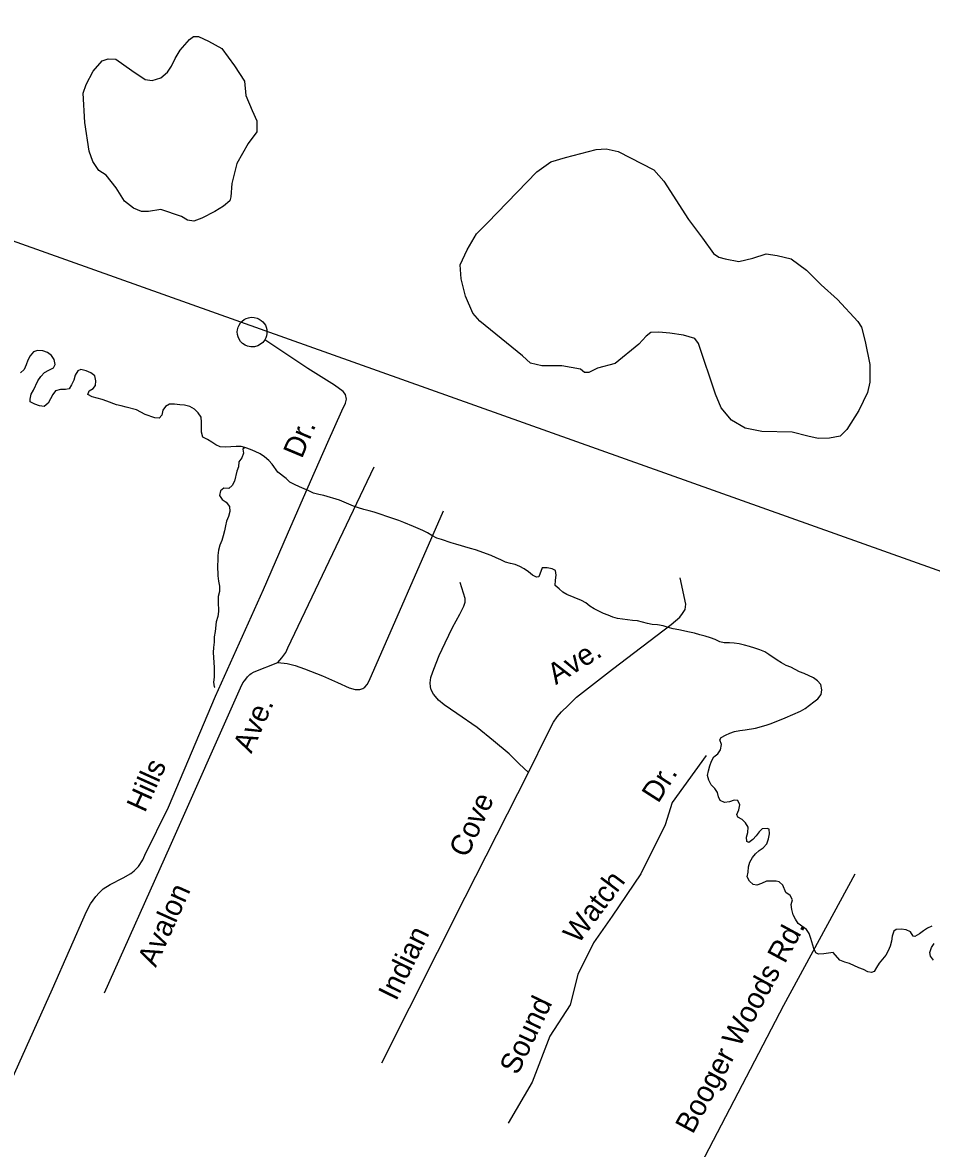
# Model space of a CAD drawing. Extents: x 2308163 to 2335412, y -96774 to 127732.
# Drawn here: x 2325975.4 to 2326033, y 123265.8 to 123337.2 of the extents above; entities that cross this region are included whole.
import ezdxf

# ---------------------------------------------------------------- set-up
doc = ezdxf.new("R2010")
doc.units = 0
for name, color, linetype in [('Old_Level_10', 7, 'Continuous'), ('Old_Level_35', 7, 'Continuous'), ('Old_Level_59', 7, 'Continuous'), ('Old_Level_60', 7, 'Continuous'), ('Old_Level_61', 7, 'Continuous'), ('Old_Level_63', 7, 'Continuous')]:
    doc.layers.add(name, color=color, linetype=linetype)

msp = doc.modelspace()

# ---------------------------------------------------------------- linework, layer by layer
at = {"layer": 'Old_Level_35'}
for points in [[(2325990.731, 123317.12), (2325990.598, 123316.949), (2325990.456, 123316.834), (2325990.282, 123316.732), (2325990.067, 123316.674), (2325989.844, 123316.669), (2325989.64, 123316.712), (2325989.478, 123316.785), (2325989.323, 123316.889), (2325989.2, 123317.015), (2325989.098, 123317.169), (2325989.032, 123317.302), (2325988.999, 123317.46), (2325988.982, 123317.623), (2325988.998, 123317.761), (2325989.033, 123317.924), (2325989.102, 123318.058), (2325989.19, 123318.197), (2325989.295, 123318.307), (2325989.417, 123318.405), (2325989.558, 123318.47), (2325989.688, 123318.52), (2325989.875, 123318.553), (2325990.054, 123318.542), (2325990.241, 123318.502), (2325990.383, 123318.438), (2325990.509, 123318.341), (2325990.603, 123318.269), (2325990.697, 123318.155), (2325990.767, 123318.05), (2325990.816, 123317.92), (2325990.853, 123317.782), (2325990.866, 123317.657), (2325990.867, 123317.51), (2325990.843, 123317.38), (2325990.803, 123317.25), (2325990.731, 123317.12)], [(2325977.276, 123275.956), (2325979.43, 123280.857), (2325979.687, 123281.344), (2325979.853, 123281.578), (2325980.018, 123281.819), (2325980.23, 123282.06), (2325980.482, 123282.294), (2325980.934, 123282.57), (2325981.758, 123283), (2325982.249, 123283.269), (2325982.455, 123283.437), (2325982.733, 123283.718), (2325983.004, 123284.146), (2325983.123, 123284.446), (2325984.62, 123287.478), (2325987.602, 123294.521), (2325990.652, 123301.291), (2325992.165, 123304.797), (2325993.623, 123308.139), (2325994.727, 123310.622), (2325995.615, 123312.62), (2325995.852, 123313.105), (2325995.907, 123313.365), (2325995.849, 123313.645), (2325995.698, 123313.831), (2325995.139, 123314.238), (2325993.457, 123315.31), (2325990.731, 123317.12)], [(2325991.555, 123296.659), (2325991.813, 123296.947), (2325992.058, 123297.301), (2325992.19, 123297.582), (2325997.651, 123309.069)], [(2325991.555, 123296.659), (2325992.155, 123296.596), (2325992.648, 123296.472), (2325993.256, 123296.255), (2325994.384, 123295.821), (2325995.345, 123295.393), (2325996.073, 123295.043), (2325996.46, 123294.952), (2325996.76, 123294.947), (2325996.946, 123295.008), (2325997.072, 123295.088), (2325997.218, 123295.262), (2325997.343, 123295.503), (2326002.055, 123306.276)], [(2326007.445, 123289.691), (2326008.645, 123292.142), (2326009.028, 123292.863), (2326009.252, 123293.211), (2326009.524, 123293.519), (2326009.948, 123293.94), (2326010.485, 123294.456), (2326012.761, 123296.226), (2326016.491, 123299.07), (2326017.035, 123299.539), (2326017.207, 123299.759), (2326017.366, 123300.02), (2326017.424, 123300.347), (2326017.062, 123302.018)], [(2326007.445, 123289.691), (2326006.849, 123290.234), (2326006.213, 123290.864), (2326005.216, 123291.698), (2326004.18, 123292.539), (2326002.903, 123293.419), (2326002.101, 123293.968), (2326001.739, 123294.272), (2326001.545, 123294.511), (2326001.424, 123294.65), (2326001.27, 123294.923), (2326001.235, 123295.122), (2326001.201, 123295.375), (2326001.253, 123295.695), (2326001.377, 123296.062), (2326001.594, 123296.623), (2326001.778, 123297.11), (2326002.154, 123297.905), (2326002.629, 123298.873), (2326003.091, 123299.715), (2326003.348, 123300.236), (2326003.427, 123300.489), (2326003.439, 123300.723), (2326003.11, 123301.725)], [(2325980.562, 123275.713), (2325984.732, 123285), (2325989.198, 123295.055), (2325989.343, 123295.369), (2325989.436, 123295.503), (2325989.522, 123295.603), (2325989.641, 123295.744), (2325989.787, 123295.891), (2325989.873, 123295.958), (2325990.052, 123296.059), (2325991.555, 123296.659)], [(2326018.699, 123290.764), (2326016.555, 123287.779), (2326016.099, 123286.367), (2326014.563, 123283.259), (2326012.736, 123280.569), (2326011.555, 123278.876), (2326010.567, 123276.871), (2326010.093, 123274.95), (2326008.8, 123272.955), (2326007.679, 123270.037), (2326006.152, 123267.439)], [(2325998.138, 123271.265), (2326003.434, 123281.783), (2326007.445, 123289.691)], [(2326017.062, 123262.313), (2326023.627, 123274.917), (2326028.142, 123283.26)], [(2325965.386, 123249.929), (2325969.926, 123259.265), (2325974.397, 123269.56), (2325977.276, 123275.956)]]:
    msp.add_lwpolyline(points, dxfattribs=at)
at = {"layer": 'Old_Level_59'}
msp.add_lwpolyline([(2325989.467, 123310.289), (2325989.331, 123310.186), (2325989.381, 123309.921), (2325989.282, 123309.629), (2325989.084, 123309.382), (2325989.061, 123309.073), (2325988.956, 123308.782), (2325988.806, 123308.157), (2325988.672, 123307.872), (2325988.456, 123307.686), (2325988.14, 123307.707), (2325987.933, 123307.532), (2325987.868, 123307.249), (2325988.034, 123306.989), (2325988.29, 123306.818), (2325988.486, 123306.552), (2325988.512, 123306.231), (2325988.422, 123305.924), (2325988.31, 123305.623), (2325988.23, 123305.321), (2325988.175, 123305.003), (2325988.093, 123304.691), (2325987.997, 123304.394), (2325987.89, 123304.103), (2325987.794, 123303.786), (2325987.762, 123303.452), (2325987.763, 123303.142), (2325987.733, 123302.798), (2325987.747, 123302.142), (2325987.803, 123301.81), (2325987.865, 123301.492), (2325987.851, 123301.158), (2325987.784, 123300.85), (2325987.773, 123300.525), (2325987.787, 123299.884), (2325987.754, 123299.565), (2325987.651, 123299.244), (2325987.595, 123298.621), (2325987.525, 123298.288), (2325987.513, 123297.948), (2325987.489, 123297.613), (2325987.452, 123297.284), (2325987.507, 123296.652), (2325987.512, 123296.337), (2325987.53, 123296.032), (2325987.52, 123295.727), (2325987.489, 123295.418), (2325987.529, 123295.117), (2325987.559, 123295.096)], dxfattribs=at)
at = {"layer": 'Old_Level_60'}
for points in [[(2325989.467, 123310.289), (2325989.224, 123310.363), (2325988.909, 123310.364), (2325988.578, 123310.329), (2325988.238, 123310.321), (2325987.903, 123310.327), (2325987.625, 123310.454), (2325987.367, 123310.625), (2325987.1, 123310.792), (2325986.813, 123310.954), (2325986.726, 123311.262), (2325986.709, 123311.888), (2325986.688, 123312.208), (2325986.515, 123312.494), (2325986.267, 123312.726), (2325985.972, 123312.899), (2325985.643, 123312.981), (2325985.339, 123313.002), (2325985.003, 123313.039), (2325984.696, 123313.044), (2325984.433, 123312.881), (2325984.264, 123312.658), (2325984.211, 123312.34), (2325984.04, 123312.152), (2325983.761, 123312.167), (2325983.151, 123312.391), (2325982.597, 123312.685), (2325981.945, 123312.84), (2325981.623, 123312.932), (2325981.325, 123313.003), (2325980.713, 123313.228), (2325980.414, 123313.324), (2325979.79, 123313.503), (2325979.506, 123313.65), (2325979.6, 123313.886), (2325979.861, 123314.034), (2325979.997, 123314.213), (2325980.024, 123314.527), (2325979.963, 123314.834), (2325979.714, 123315.025), (2325979.415, 123315.142), (2325979.079, 123315.23), (2325978.883, 123315.145), (2325978.713, 123314.872), (2325978.623, 123314.56), (2325978.487, 123314.27), (2325978.333, 123314.006), (2325978.098, 123313.958), (2325977.785, 123313.959), (2325977.469, 123313.878), (2325977.289, 123313.656), (2325976.998, 123313.112), (2325976.746, 123312.897), (2325976.442, 123312.923), (2325976.156, 123313.029), (2325975.87, 123313.176), (2325975.856, 123313.36), (2325975.919, 123313.667), (2325976.067, 123313.931), (2325976.347, 123314.521), (2325976.531, 123314.789), (2325976.765, 123315.04), (2325977.037, 123315.189), (2325977.33, 123315.336), (2325977.445, 123315.551), (2325977.388, 123315.873), (2325977.203, 123316.123), (2325976.96, 123316.309), (2325976.652, 123316.411), (2325976.33, 123316.432), (2325976.061, 123316.366), (2325975.863, 123316.113), (2325975.709, 123315.834), (2325975.616, 123315.537), (2325975.49, 123315.232), (2325975.238, 123315.017)], [(2325995.455, 123306.952), (2325994.478, 123307.25), (2325994.149, 123307.317), (2325993.817, 123307.4), (2325993.512, 123307.532), (2325993.22, 123307.674), (2325992.928, 123307.806), (2325992.603, 123307.945), (2325992.312, 123308.102), (2325992.074, 123308.324), (2325991.563, 123308.722), (2325991.195, 123309.233), (2325990.981, 123309.464), (2325990.719, 123309.702), (2325990.443, 123309.899), (2325990.125, 123310.047), (2325989.82, 123310.17), (2325989.525, 123310.271), (2325989.467, 123310.289)], [(2326014.359, 123299.293), (2326014.035, 123299.325), (2326013.402, 123299.402), (2326013.08, 123299.449), (2326012.78, 123299.536), (2326012.498, 123299.662), (2326012.197, 123299.774), (2326011.597, 123300.054), (2326011.335, 123300.226), (2326011.076, 123300.433), (2326010.794, 123300.585), (2326009.876, 123300.962), (2326009.616, 123301.123), (2326009.376, 123301.32), (2326009.14, 123301.546), (2326009.156, 123301.871), (2326009.193, 123302.185), (2326009.161, 123302.491), (2326008.933, 123302.605), (2326008.624, 123302.667), (2326008.309, 123302.667), (2326008.104, 123302.08), (2326007.951, 123302.06), (2326007.706, 123302.205), (2326007.453, 123302.407), (2326007.175, 123302.605), (2326006.889, 123302.752), (2326006.603, 123302.863), (2326006.292, 123302.935), (2326005.986, 123303.027), (2326005.682, 123303.159), (2326005.384, 123303.302), (2326005.069, 123303.435), (2326004.092, 123303.793), (2326003.76, 123303.896), (2326002.84, 123304.152), (2326002.541, 123304.243), (2326001.937, 123304.462), (2326001.626, 123304.549), (2326001.31, 123304.702), (2326001.046, 123304.874), (2326000.747, 123305.027), (2326000.149, 123305.281), (2325999.532, 123305.526), (2325999.215, 123305.659), (2325998.913, 123305.771), (2325997.651, 123306.2), (2325997.345, 123306.282), (2325997, 123306.36), (2325996.668, 123306.463), (2325996.355, 123306.575), (2325996.056, 123306.692), (2325995.766, 123306.824), (2325995.455, 123306.952)], [(2326021.386, 123283.69), (2326021.466, 123283.998), (2326021.648, 123284.281), (2326021.833, 123284.524), (2326022.064, 123284.729), (2326022.319, 123284.913), (2326022.538, 123285.165), (2326022.649, 123285.476), (2326022.725, 123285.783), (2326022.705, 123286.089), (2326022.56, 123286.13), (2326022.244, 123286.115), (2326022.052, 123285.918), (2326021.867, 123285.671), (2326021.67, 123285.439), (2326021.405, 123285.235), (2326021.275, 123285.3), (2326021.256, 123285.59), (2326021.344, 123285.882), (2326021.361, 123286.217), (2326021.204, 123286.491), (2326020.994, 123286.707), (2326020.699, 123286.859), (2326020.639, 123287.024), (2326020.781, 123287.309), (2326020.827, 123287.627), (2326020.702, 123287.911), (2326020.477, 123287.929), (2326020.185, 123287.812), (2326019.869, 123287.787), (2326019.582, 123287.909), (2326019.489, 123288.146), (2326019.427, 123288.423), (2326019.253, 123288.677), (2326019.009, 123288.904), (2326018.879, 123289.188), (2326018.788, 123289.496), (2326018.849, 123289.794), (2326018.932, 123290.101), (2326019.044, 123290.402), (2326019.198, 123290.681), (2326019.442, 123290.866), (2326019.612, 123291.124), (2326019.664, 123291.448), (2326019.567, 123291.756), (2326019.651, 123291.906), (2326019.923, 123292.054), (2326020.209, 123292.171), (2326020.497, 123292.273), (2326020.837, 123292.342), (2326021.178, 123292.386), (2326021.824, 123292.491), (2326022.497, 123292.681), (2326022.817, 123292.782), (2326023.718, 123293.147), (2326024.688, 123293.561), (2326024.979, 123293.744), (2326025.25, 123293.958), (2326025.527, 123294.162), (2326025.772, 123294.357), (2326025.99, 123294.619), (2326026.029, 123294.927), (2326025.976, 123295.259), (2326025.756, 123295.491), (2326025.498, 123295.682), (2326024.915, 123295.962), (2326024.62, 123296.073), (2326024.34, 123296.21), (2326024.063, 123296.357), (2326023.772, 123296.474), (2326023.475, 123296.626), (2326023.206, 123296.798), (2326022.68, 123297.172), (2326022.42, 123297.338), (2326022.107, 123297.466), (2326021.785, 123297.569), (2326021.458, 123297.666), (2326021.133, 123297.749), (2326020.803, 123297.841), (2326020.487, 123297.883), (2326020.177, 123297.903), (2326019.836, 123297.905), (2326019.572, 123297.975), (2326019.268, 123298.123), (2326018.967, 123298.23), (2326018.629, 123298.328), (2326018.31, 123298.405), (2326017.968, 123298.508), (2326017.652, 123298.59), (2326016.964, 123298.731), (2326016.62, 123298.793), (2326016.288, 123298.881), (2326015.967, 123298.989), (2326015.623, 123299.036), (2326015.282, 123299.068), (2326014.977, 123299.124), (2326014.67, 123299.221), (2326014.359, 123299.293)], [(2326033.012, 123279.931), (2326032.732, 123279.808), (2326032.47, 123279.645), (2326032.219, 123279.445), (2326031.934, 123279.272), (2326031.832, 123279.306), (2326031.652, 123279.571), (2326031.384, 123279.708), (2326031.064, 123279.739), (2326030.741, 123279.735), (2326030.587, 123279.628), (2326030.499, 123279.306), (2326030.445, 123278.978), (2326030.369, 123278.67), (2326030.231, 123278.381), (2326030.083, 123278.106), (2326029.668, 123277.597), (2326029.507, 123277.318), (2326029.34, 123277.065), (2326029.173, 123276.989), (2326028.959, 123277.047), (2326028.675, 123277.179), (2326028.37, 123277.301), (2326027.788, 123277.565), (2326027.481, 123277.657), (2326027.177, 123277.774), (2326026.75, 123278.267), (2326026.163, 123278.175), (2326025.827, 123278.151), (2326025.662, 123278.248), (2326025.529, 123278.522), (2326025.344, 123279.164), (2326025.228, 123279.463), (2326025.062, 123279.727), (2326024.527, 123280.112), (2326024.355, 123280.372), (2326024.218, 123280.666), (2326024.13, 123280.984), (2326024.098, 123281.31), (2326024.166, 123281.608), (2326024.023, 123281.877), (2326023.761, 123282.079), (2326023.561, 123282.528), (2326023.337, 123282.749), (2326023.144, 123282.797), (2326022.521, 123282.782), (2326022.202, 123282.651), (2326021.907, 123282.544), (2326021.679, 123282.573), (2326021.451, 123282.794), (2326021.3, 123283.068), (2326021.367, 123283.371), (2326021.386, 123283.69)], [(2326033.105, 123277.783), (2326032.926, 123278.028), (2326032.873, 123278.269), (2326032.977, 123278.58), (2326033.155, 123278.828)]]:
    msp.add_lwpolyline(points, dxfattribs=at)
at = {"layer": 'Old_Level_61'}
for points in [[(2325990.222, 123330.302), (2325989.675, 123329.574), (2325988.96, 123328.293), (2325988.639, 123327.024), (2325988.587, 123326.187), (2325988.51, 123325.941), (2325988.112, 123325.584), (2325987.561, 123325.262), (2325986.738, 123324.823), (2325986.223, 123324.643), (2325985.834, 123324.707), (2325985.447, 123324.939), (2325984.145, 123325.38), (2325983.355, 123325.26), (2325982.915, 123325.25), (2325982.415, 123325.46), (2325981.829, 123325.902), (2325981.303, 123326.759), (2325980.684, 123327.568), (2325980.209, 123327.858), (2325979.821, 123328.426), (2325979.604, 123329.083), (2325979.32, 123330.892), (2325979.222, 123332.76), (2325979.403, 123333.308), (2325979.848, 123334.156), (2325980.425, 123334.802), (2325980.795, 123334.942), (2325981.284, 123334.92), (2325982.299, 123334.194), (2325983.158, 123333.62), (2325983.594, 123333.57), (2325984.133, 123333.734), (2325984.561, 123334.09), (2325984.823, 123334.482), (2325985.053, 123334.962), (2325985.372, 123335.49), (2325985.95, 123336.161), (2325986.211, 123336.35), (2325986.536, 123336.344), (2325987.171, 123336.048), (2325988.011, 123335.597), (2325988.804, 123334.487), (2325989.441, 123333.525), (2325989.526, 123332.613), (2325989.932, 123331.664), (2325990.233, 123331.013), (2325990.222, 123330.302)], [(2326029.073, 123314.425), (2326028.932, 123313.78), (2326028.384, 123312.64), (2326027.622, 123311.442), (2326027.195, 123311.005), (2326026.52, 123310.88), (2326025.804, 123310.865), (2326025.137, 123310.999), (2326024.153, 123311.257), (2326022.224, 123311.308), (2326021.179, 123311.507), (2326020.301, 123312.015), (2326019.653, 123312.804), (2326019.29, 123313.681), (2326018.222, 123316.878), (2326017.978, 123317.201), (2326017.269, 123317.419), (2326016.395, 123317.551), (2326015.7, 123317.605), (2326015.195, 123317.592), (2326014.909, 123317.353), (2326014.43, 123316.851), (2326012.931, 123315.622), (2326011.811, 123315.315), (2326011.267, 123315.04), (2326010.993, 123315.049), (2326010.746, 123315.256), (2326009.551, 123315.47), (2326008.286, 123315.462), (2326007.569, 123315.635), (2326007.054, 123316.099), (2326004.356, 123318.311), (2326003.907, 123318.81), (2326003.44, 123319.893), (2326003.178, 123320.989), (2326003.114, 123321.87), (2326003.564, 123322.825), (2326004.154, 123323.836), (2326004.853, 123324.529), (2326007.962, 123327.775), (2326008.865, 123328.41), (2326009.79, 123328.672), (2326011.735, 123329.195), (2326012.356, 123329.224), (2326013.117, 123329.05), (2326015.388, 123327.89), (2326016.03, 123327.177), (2326017.591, 123324.755), (2326018.475, 123323.566), (2326019.157, 123322.582), (2326019.497, 123322.362), (2326019.905, 123322.252), (2326020.782, 123322.094), (2326021.667, 123322.287), (2326022.509, 123322.578), (2326023.208, 123322.458), (2326024.092, 123322.249), (2326025.061, 123321.525), (2326025.99, 123320.604), (2326027.032, 123319.684), (2326028.307, 123318.288), (2326028.543, 123317.929), (2326028.789, 123317.011), (2326029.085, 123315.548), (2326029.073, 123314.425)]]:
    msp.add_lwpolyline(points, dxfattribs=at)
at = {"layer": 'Old_Level_63'}
msp.add_line((2326051.481, 123296.047), (2325935.849, 123337.24), dxfattribs=at)

# ---------------------------------------------------------------- texts
at = {"layer": 'Old_Level_10'}
for s, height, rotation, p in [('Dr.', 1.3328, 67.31688, (2325993.078, 123309.537)), ('Ave.', 1.3328, 32.04993, (2326009.176, 123295.215)), ('Ave.', 1.3328, 66.05059, (2325989.877, 123290.837)), ('Hills', 1.3328, 65.64113, (2325983.13, 123287.085)), ('Dr.', 1.3328, 57.31714, (2326015.657, 123287.679)), ('Cove', 1.3328, 65.514, (2326003.561, 123284.216)), ('Watch', 1.3328, 53.11391, (2326010.601, 123278.756)), ('Avalon', 1.3328, 65.81929, (2325983.82, 123277.275)), ('Indian ', 1.3328, 63.79948, (2325999.049, 123275.141)), ('Booger Woods Rd.', 1.33284, 61.62421, (2326017.849, 123266.699)), ('Sound ', 1.3328, 64.33474, (2326006.748, 123270.439))]:
    msp.add_text(s, height=height, rotation=rotation, dxfattribs=at).set_placement(p)

doc.saveas('drawing.dxf')
